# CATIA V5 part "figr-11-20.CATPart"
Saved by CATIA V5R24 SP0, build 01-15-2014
Part number: Part5
Bounding box of the stored display mesh (mm): x -70 to 70, y -150 to 0, z -1.939 to 20.996
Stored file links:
  D:\KAVITA\CATIA V5-6R2014 Project_ Kavita\CATIA V5-6R2014_partfiles\Partfiles\c11_catia_v5-6r2014_prt\figr-11-20.CATPart
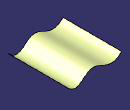
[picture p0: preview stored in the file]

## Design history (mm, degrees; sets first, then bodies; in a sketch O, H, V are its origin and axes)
Body1 (main body)
  Sketch1 on zx-plane, origin (0, 0, 0), H (-1, 0, 0), V (0, 0, 1)
    spline S1 through (-70, 10) (-40, 0) (-10, 20) (30, 10) (70, 20)
  Extrude1: Element1 Sketch1, Lim1 150, Lim2 0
